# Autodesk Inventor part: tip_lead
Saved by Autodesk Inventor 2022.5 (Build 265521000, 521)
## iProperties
Created: 2024-12
Part Number: tip_lead
Material: Generic
Document SubType Name: Modeling
Designer: AdminForWorker
Density: 1 g/cm^3
Appearance: Default
Title: tip_lead
Author: AdminForWorker
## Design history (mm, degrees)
feature "Body1"
body "Solid1"
